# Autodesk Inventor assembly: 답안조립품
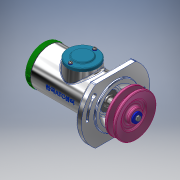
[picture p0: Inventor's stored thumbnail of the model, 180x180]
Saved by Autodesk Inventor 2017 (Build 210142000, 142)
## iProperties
Part Number: 답안조립품
Material: 일반
Document SubType Name: Assembly
Designer: MRC
Author: MRC
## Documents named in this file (22)
- C:\Users\MRC\Desktop\720506V1002\답안조립품.iam
- C:\Users\MRC\Desktop\720506V1002\본체.ipt
- C:\Users\MRC\Desktop\720506V1002\개스킷.ipt
- C:\Users\MRC\Desktop\720506V1002\사이드 커버.ipt
- 사이드 커버.ipt
- C:\Users\MRC\Desktop\720506V1002\축.ipt
- C:\Users\MRC\Desktop\720506V1002\멈춤링 35 x 1.6.ipt
- C:\Users\MRC\Desktop\720506V1002\멈춤링 15 x 1.ipt
- C:\Users\MRC\Desktop\720506V1002\베어링 6202.ipt
- C:\Users\MRC\Desktop\720506V1002\부시1.ipt
- C:\Users\MRC\Desktop\720506V1002\부시2.ipt
- C:\Users\MRC\Desktop\720506V1002\와셔 10 x 21.ipt
- C:\Users\MRC\Desktop\720506V1002\너트 M10.ipt
- C:\Users\MRC\Desktop\720506V1002\오일 실 15 x 30 x 7.ipt
- C:\Users\MRC\Desktop\720506V1002\Ű 4 x 4.ipt
- C:\Users\MRC\Desktop\720506V1002\V-벨트풀리.ipt
- C:\Users\MRC\Desktop\720506V1002\멈춤나사 M3.ipt
- C:\Users\MRC\Desktop\720506V1002\와셔 4 x 16.ipt
- C:\Users\MRC\Desktop\720506V1002\볼트 M4 x 10.ipt
- C:\Users\MRC\Desktop\720506V1002\탑 커버.ipt
- C:\Users\MRC\Desktop\720506V1002\와셔 3 x 6.ipt
- C:\Users\MRC\Desktop\720506V1002\십자볼트 M3 x 10.ipt
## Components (4 placed, 4 different names)
1. 개스킷:1
2. Ű 4 x 4:1
3. V-벨트풀리:1
4. ISO 4017 M4 x 10:1
